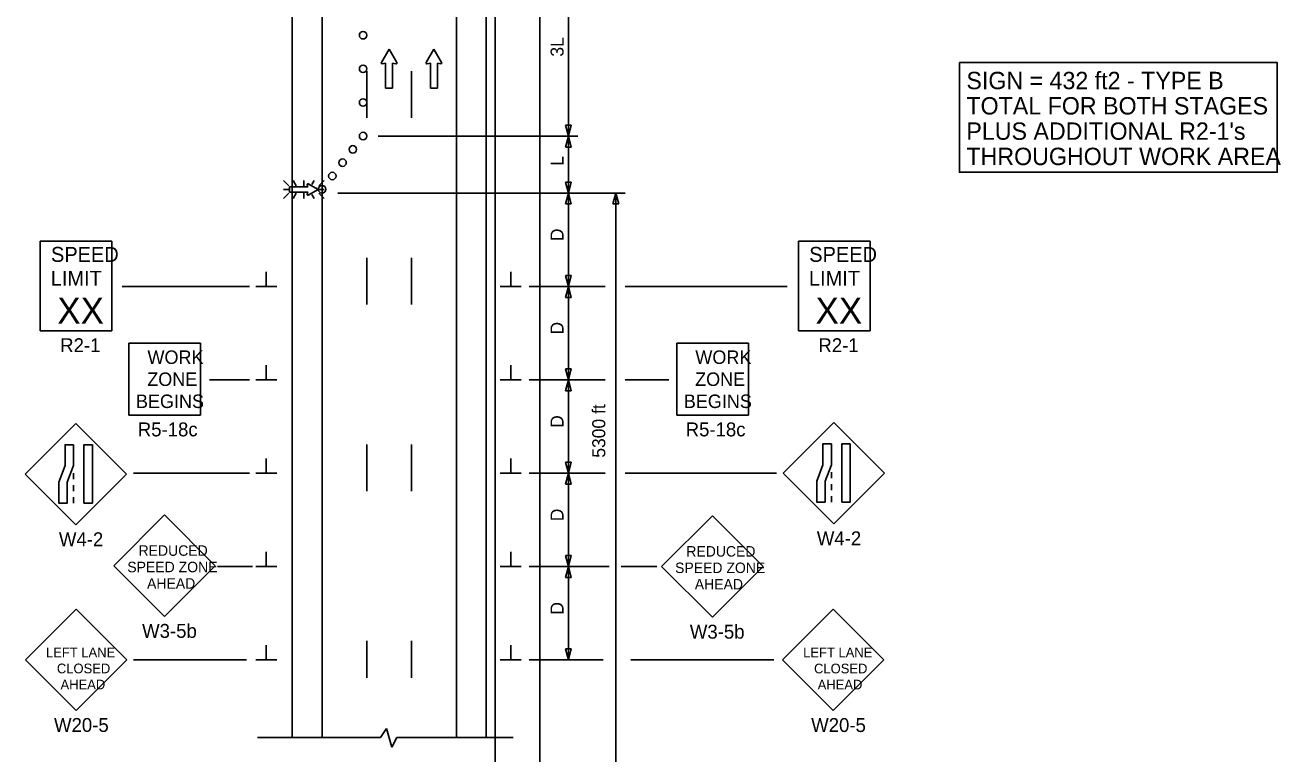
# Model space of a CAD drawing. Extents: x 16590 to 19508, y 5703 to 6974.
# Drawn here: x 16729 to 17402, y 6255 to 6645 of the extents above; entities that cross this region are included whole.
import ezdxf

# ---------------------------------------------------------------- set-up
doc = ezdxf.new("R2010")
doc.units = 0
for name, color, linetype in [('ALI_LEGAL_EX', 7, 'Continuous'), ('MT_SCRATCH_LEVEL_E', 7, 'Continuous'), ('PAVT_EDGE_EX', 7, 'Continuous'), ('TRAFFIC_SIGNS_PR', 7, 'Continuous'), ('TYPICAL_TEXT_DIMEN_EX', 7, 'Continuous'), ('TYPICAL_TEXT_DIMEN_PR', 7, 'Continuous')]:
    doc.layers.add(name, color=color, linetype=linetype)

msp = doc.modelspace()

# ---------------------------------------------------------------- linework, layer by layer
at = {"layer": 'ALI_LEGAL_EX'}
for p, q in [((16980.68, 6974.12), (16980.68, 6155.98)), ((17004.68, 6974.12), (17004.68, 6155.98)), ((16980.68, 6922.21), (16980.68, 6058.3)), ((17004.68, 6922.21), (17004.68, 6058.3))]:
    msp.add_line(p, q, dxfattribs=at)
for points in [[(16911.96, 6620.69), (16911.96, 6595.69)], [(16935.96, 6620.69), (16935.96, 6595.69)], [(16911.96, 6520.69), (16911.96, 6495.69)], [(16935.96, 6520.69), (16935.96, 6495.69)], [(16911.96, 6420.69), (16911.96, 6395.69)], [(16935.96, 6420.69), (16935.96, 6395.69)], [(16911.96, 6315.64), (16911.96, 6295.69)], [(16935.96, 6315.64), (16935.96, 6295.69)]]:
    msp.add_lwpolyline(points, dxfattribs=at)
at = {"layer": 'MT_SCRATCH_LEVEL_E'}
for p, q in [((16923.86, 6632.49), (16919.75, 6625.25)), ((16928.01, 6625.25), (16923.86, 6632.49)), ((16947.91, 6632.49), (16943.8, 6625.25)), ((16952.06, 6625.25), (16947.91, 6632.49)), ((16920.23, 6624.57), (16922.01, 6624.88)), ((16922.01, 6624.88), (16922.01, 6611.63)), ((16925.75, 6611.63), (16925.75, 6624.88)), ((16925.75, 6624.88), (16927.53, 6624.57)), ((16944.28, 6624.57), (16946.06, 6624.88)), ((16946.06, 6624.88), (16946.06, 6611.63)), ((16949.8, 6611.63), (16949.8, 6624.88)), ((16949.8, 6624.88), (16951.58, 6624.57)), ((16922.01, 6611.63), (16925.75, 6611.63)), ((16946.06, 6611.63), (16949.8, 6611.63))]:
    msp.add_line(p, q, dxfattribs=at)
for centre, start, end in [((16920.16, 6625.03), 150.42484, 279.96381), ((16927.6, 6625.03), 260.03619, 29.77312), ((16944.21, 6625.03), 150.42484, 279.96381), ((16951.65, 6625.03), 260.03619, 29.77312)]:
    msp.add_arc(centre, 0.463, start, end, dxfattribs=at)
at = {"layer": 'PAVT_EDGE_EX'}
for p, q in [((16871.96, 6927.73), (16871.96, 6263.8)), ((16887.96, 6927.73), (16887.96, 6263.8)), ((16959.96, 6927.73), (16959.96, 6263.8)), ((16975.96, 6927.73), (16975.96, 6263.8))]:
    msp.add_line(p, q, dxfattribs=at)
at = {"layer": 'TRAFFIC_SIGNS_PR'}
for p, q in [((16870.12, 6559.34), (16867.3, 6562.16)), ((16870.12, 6557.31), (16867.3, 6557.31)), ((16874.07, 6559.34), (16872.44, 6562.16)), ((16878.2, 6559.34), (16878.2, 6562.16)), ((16882.39, 6559.98), (16883.65, 6562.16)), ((16889.11, 6562.16), (16886.29, 6559.34)), ((16886.29, 6557.31), (16889.11, 6557.31)), ((16870.12, 6555.28), (16867.3, 6552.46)), ((16872.42, 6552.46), (16874.04, 6555.28)), ((16878.2, 6555.28), (16878.2, 6552.46)), ((16883.67, 6552.46), (16882.47, 6554.55)), ((16889.11, 6552.46), (16886.29, 6555.28)), ((16736.89, 6529.7), (16775.34, 6529.7)), ((16736.89, 6481.64), (16736.89, 6529.7)), ((16775.34, 6481.64), (16775.34, 6529.7)), ((17143.29, 6529.7), (17181.74, 6529.7)), ((17143.29, 6481.64), (17143.29, 6529.7)), ((17181.74, 6481.64), (17181.74, 6529.7)), ((16736.89, 6481.64), (16775.34, 6481.64)), ((17143.29, 6481.64), (17181.74, 6481.64)), ((16784.39, 6436.53), (16784.39, 6474.93)), ((16784.39, 6474.93), (16822.79, 6474.93)), ((16822.79, 6436.53), (16822.79, 6474.93)), ((17078.04, 6436.53), (17078.04, 6474.93)), ((17078.04, 6474.93), (17116.44, 6474.93)), ((17116.44, 6436.53), (17116.44, 6474.93)), ((16784.39, 6436.53), (16822.79, 6436.53)), ((17078.04, 6436.53), (17116.44, 6436.53)), ((16755.95, 6432), (16728.79, 6404.85)), ((16783.1, 6404.85), (16755.95, 6432)), ((17162.19, 6432.52), (17135.04, 6405.37)), ((17189.35, 6405.37), (17162.19, 6432.52)), ((16728.79, 6404.85), (16755.95, 6377.7)), ((16754.7, 6405.34), (16754.7, 6402.14)), ((16755.95, 6377.7), (16783.1, 6404.85)), ((17135.04, 6405.37), (17162.19, 6378.21)), ((17160.95, 6405.86), (17160.95, 6402.66)), ((17162.19, 6378.21), (17189.35, 6405.37)), ((16754.7, 6398.94), (16754.7, 6395.74)), ((17160.95, 6399.46), (17160.95, 6396.26)), ((16754.7, 6392.54), (16754.7, 6389.34)), ((17160.95, 6393.06), (17160.95, 6389.86)), ((16803.56, 6383), (16776.37, 6355.82)), ((16830.74, 6355.82), (16803.56, 6383)), ((17097.14, 6382.59), (17069.96, 6355.4)), ((17124.33, 6355.4), (17097.14, 6382.59)), ((16776.37, 6355.82), (16803.56, 6328.63)), ((16803.56, 6328.63), (16830.74, 6355.82)), ((17069.96, 6355.4), (17097.14, 6328.21)), ((17097.14, 6328.21), (17124.33, 6355.4)), ((16756.12, 6332.56), (16728.97, 6305.4)), ((16783.27, 6305.4), (16756.12, 6332.56)), ((17161.94, 6332.51), (17134.79, 6305.36)), ((17189.09, 6305.36), (17161.94, 6332.51)), ((16728.97, 6305.4), (16756.12, 6278.25)), ((16756.12, 6278.25), (16783.27, 6305.4)), ((17134.79, 6305.36), (17161.94, 6278.21)), ((17161.94, 6278.21), (17189.09, 6305.36))]:
    msp.add_line(p, q, dxfattribs=at)
for points in [[(16880.03, 6554.63), (16880.26, 6555.93), (16870.54, 6555.93), (16870.54, 6558.67), (16880.26, 6558.67), (16880.03, 6559.97)], [(16880.53, 6560.33), (16885.84, 6557.31), (16880.53, 6554.27)]]:
    msp.add_lwpolyline(points, dxfattribs=at)
for points in [[(16754.7, 6420.59), (16754.7, 6409.41), (16751.36, 6400.52), (16751.36, 6389.34), (16746.86, 6389.34), (16746.86, 6400.52), (16750.21, 6409.41), (16750.21, 6420.59)], [(16764.84, 6420.59), (16764.84, 6389.34), (16760.34, 6389.34), (16760.34, 6420.59)], [(17160.95, 6421.1), (17160.95, 6409.92), (17157.6, 6401.04), (17157.6, 6389.86), (17153.11, 6389.86), (17153.11, 6401.04), (17156.45, 6409.92), (17156.45, 6421.1)], [(17171.08, 6421.1), (17171.08, 6389.86), (17166.59, 6389.86), (17166.59, 6421.1)]]:
    msp.add_lwpolyline(points, close=True, dxfattribs=at)
for centre in [(16909.95, 6639.92), (16909.95, 6621.92), (16909.95, 6603.92), (16909.95, 6585.92), (16909.95, 6585.92), (16909.95, 6585.92), (16909.95, 6585.92), (16904.45, 6578.79), (16898.95, 6571.66), (16893.46, 6564.53), (16887.96, 6557.41)]:
    msp.add_circle(centre, 2, dxfattribs=at)
for centre, start, end in [((16880.37, 6560.03), 61.10835, 189.26922), ((16880.37, 6554.57), 170.04067, 298.51671)]:
    msp.add_arc(centre, 0.341, start, end, dxfattribs=at)
at = {"layer": 'TYPICAL_TEXT_DIMEN_EX'}
msp.add_lwpolyline([(17229.59, 6625.26), (17399.96, 6625.26), (17399.96, 6566.51), (17229.59, 6566.51)], close=True, dxfattribs=at)
at = {"layer": 'TYPICAL_TEXT_DIMEN_PR'}
for p, q in [((17020.05, 6677.97), (17019.96, 6585.92)), ((17019.96, 6585.92), (17018.39, 6591.78)), ((17018.39, 6591.78), (17019.96, 6591.78)), ((17019.96, 6591.78), (17021.53, 6591.78)), ((17021.53, 6591.78), (17019.96, 6585.92)), ((17024.96, 6585.92), (16918.04, 6585.92)), ((17018.39, 6580.06), (17019.96, 6585.92)), ((17019.96, 6555.41), (17019.96, 6585.92)), ((17019.96, 6585.92), (17021.53, 6580.06)), ((17019.96, 6580.06), (17018.39, 6580.06)), ((17021.53, 6580.06), (17019.96, 6580.06)), ((17019.96, 6555.41), (17018.39, 6561.27)), ((17018.39, 6561.27), (17019.96, 6561.27)), ((17019.96, 6561.27), (17021.53, 6561.27)), ((17021.53, 6561.27), (17019.96, 6555.41)), ((16896.35, 6555.41), (17050.39, 6555.41)), ((17018.39, 6549.55), (17019.96, 6555.41)), ((17019.96, 6549.55), (17018.39, 6549.55)), ((17019.96, 6555.41), (17019.96, 6505.41)), ((17019.96, 6555.41), (17021.53, 6549.55)), ((17021.53, 6549.55), (17019.96, 6549.55)), ((17043.82, 6549.55), (17045.39, 6555.41)), ((17045.39, 6549.55), (17043.82, 6549.55)), ((17045.39, 6555.41), (17045.39, 6202.2)), ((17045.39, 6555.41), (17046.96, 6549.55)), ((17046.96, 6549.55), (17045.39, 6549.55)), ((16858.07, 6505.41), (16858.07, 6513.19)), ((16989.08, 6505.41), (16989.08, 6513.19)), ((17019.96, 6505.41), (17018.39, 6511.27)), ((17018.39, 6511.27), (17019.96, 6511.27)), ((17019.96, 6511.27), (17021.53, 6511.27)), ((17021.53, 6511.27), (17019.96, 6505.41)), ((16849.02, 6505.41), (16780.84, 6505.41)), ((16863.7, 6505.41), (16852.45, 6505.41)), ((16994.71, 6505.41), (16983.46, 6505.41)), ((17039.74, 6505.41), (16998.96, 6505.41)), ((17018.39, 6499.55), (17019.96, 6505.41)), ((17019.96, 6505.41), (17019.96, 6455.41)), ((17019.96, 6505.41), (17021.53, 6499.55)), ((17137.17, 6505.41), (17050.39, 6505.41)), ((17019.96, 6499.55), (17018.39, 6499.55)), ((17021.53, 6499.55), (17019.96, 6499.55)), ((16858.07, 6455.41), (16858.07, 6463.19)), ((16989.08, 6455.41), (16989.08, 6463.19)), ((16849.02, 6455.41), (16827.64, 6455.41)), ((16863.7, 6455.41), (16852.45, 6455.41)), ((16994.71, 6455.41), (16983.46, 6455.41)), ((17039.74, 6455.41), (16998.96, 6455.41)), ((17019.96, 6455.41), (17018.39, 6461.27)), ((17018.39, 6461.27), (17019.96, 6461.27)), ((17018.39, 6449.55), (17019.96, 6455.41)), ((17019.96, 6461.27), (17021.53, 6461.27)), ((17021.53, 6461.27), (17019.96, 6455.41)), ((17019.96, 6455.41), (17019.96, 6405.41)), ((17019.96, 6455.41), (17021.53, 6449.55)), ((17073.74, 6455.41), (17050.45, 6455.41)), ((17019.96, 6449.55), (17018.39, 6449.55)), ((17021.53, 6449.55), (17019.96, 6449.55)), ((16858.07, 6405.41), (16858.07, 6413.19)), ((16989.08, 6405.41), (16989.08, 6413.19)), ((17019.96, 6405.41), (17018.39, 6411.27)), ((17018.39, 6411.27), (17019.96, 6411.27)), ((17019.96, 6411.27), (17021.53, 6411.27)), ((17021.53, 6411.27), (17019.96, 6405.41)), ((16849.02, 6405.41), (16786.8, 6405.41)), ((16863.7, 6405.41), (16852.45, 6405.41)), ((16994.71, 6405.41), (16983.46, 6405.41)), ((17039.74, 6405.41), (16998.96, 6405.41)), ((17018.39, 6399.55), (17019.96, 6405.41)), ((17019.96, 6405.41), (17019.96, 6355.41)), ((17019.96, 6405.41), (17021.53, 6399.55)), ((17131.57, 6405.41), (17050.39, 6405.41)), ((17019.96, 6399.55), (17018.39, 6399.55)), ((17021.53, 6399.55), (17019.96, 6399.55)), ((16858.07, 6355.41), (16858.07, 6363.19)), ((16989.08, 6355.41), (16989.08, 6363.19)), ((17019.96, 6355.41), (17018.39, 6361.27)), ((17018.39, 6361.27), (17019.96, 6361.27)), ((17019.96, 6361.27), (17021.53, 6361.27)), ((17021.53, 6361.27), (17019.96, 6355.41)), ((16850.63, 6355.41), (16831.98, 6355.41)), ((16863.7, 6355.41), (16852.45, 6355.41)), ((16994.71, 6355.41), (16983.46, 6355.41)), ((17041.77, 6355.41), (16998.96, 6355.41)), ((17018.39, 6349.55), (17019.96, 6355.41)), ((17019.96, 6355.41), (17019.96, 6305.41)), ((17019.96, 6355.41), (17021.53, 6349.55)), ((17067.45, 6355.41), (17048.36, 6355.41)), ((17019.96, 6349.55), (17018.39, 6349.55)), ((17021.53, 6349.55), (17019.96, 6349.55)), ((16858.07, 6305.41), (16858.07, 6313.19)), ((16989.08, 6305.41), (16989.08, 6313.19)), ((17019.96, 6305.41), (17018.39, 6311.27)), ((17018.39, 6311.27), (17019.96, 6311.27)), ((17019.96, 6311.27), (17021.53, 6311.27)), ((17021.53, 6311.27), (17019.96, 6305.41)), ((16786.8, 6305.41), (16847.41, 6305.41)), ((16863.7, 6305.41), (16852.45, 6305.41)), ((16994.71, 6305.41), (16983.46, 6305.41)), ((17038.56, 6305.41), (16998.96, 6305.41)), ((17130.13, 6305.41), (17053.51, 6305.41)), ((16922.56, 6268.6), (16919.31, 6263.8)), ((16925.3, 6258.66), (16922.56, 6268.6)), ((16919.31, 6263.8), (16853.36, 6263.8)), ((16928.05, 6263.8), (16925.3, 6258.66)), ((16990.38, 6263.8), (16928.05, 6263.8))]:
    msp.add_line(p, q, dxfattribs=at)

# ---------------------------------------------------------------- texts
at = {"layer": 'TRAFFIC_SIGNS_PR'}
for s, height, p in [('SPEED', 8.01, (16742.67, 6518.55)), ('SPEED', 8.01, (17149.07, 6518.55)), ('LIMIT', 8.01, (16742.51, 6505.73)), ('LIMIT', 8.01, (17148.91, 6505.73)), ('XX', 14.048, (16746.02, 6485.4)), ('XX', 14.048, (17152.42, 6485.4)), ('R2-1', 7.449, (16747.58, 6470.19)), ('R2-1', 7.449, (17153.98, 6470.19)), ('WORK', 7.217, (16794.39, 6463.89)), ('WORK', 7.217, (17088.04, 6463.89)), ('ZONE', 7.217, (16794.27, 6452.08)), ('ZONE', 7.217, (17087.92, 6452.08)), ('BEGINS', 7.217, (16788.2, 6440.27)), ('BEGINS', 7.217, (17081.85, 6440.27)), ('R5-18c', 7.44, (16789.2, 6425.09)), ('R5-18c', 7.44, (17082.85, 6425.09)), ('W4-2', 7.44, (17153.15, 6366.77)), ('W4-2', 7.44, (16746.91, 6366.26)), ('REDUCED', 5.607, (16789.6, 6361.13)), ('REDUCED', 5.607, (17083.18, 6360.71)), ('SPEED ZONE', 5.607, (16783.58, 6352.32)), ('SPEED ZONE', 5.607, (17077.17, 6351.9)), ('AHEAD', 5.607, (16794.15, 6343.51)), ('AHEAD', 5.607, (17087.74, 6343.09)), ('W3-5b', 7.449, (16791.49, 6317.18)), ('W3-5b', 7.449, (17085.08, 6316.76)), ('LEFT LANE', 5.2, (16740, 6306.8)), ('LEFT LANE', 5.2, (17145.82, 6306.76)), ('CLOSED', 5.2, (16745.83, 6298.2)), ('CLOSED', 5.2, (17151.66, 6298.16)), ('AHEAD', 5.2, (16747.78, 6289.6)), ('AHEAD', 5.2, (17153.6, 6289.56)), ('W20-5', 7.44, (16744.29, 6266.81)), ('W20-5', 7.44, (17150.12, 6266.77))]:
    msp.add_text(s, height=height, dxfattribs=at).set_placement(p)
at = {"layer": 'TYPICAL_TEXT_DIMEN_EX'}
for s, p in [('SIGN = 432 ft2 - TYPE B', (17233.32, 6611.02)), ('TOTAL FOR BOTH STAGES', (17233.32, 6597.47)), ("PLUS ADDITIONAL R2-1's", (17233.32, 6583.92)), ('THROUGHOUT WORK AREA', (17233.32, 6570.37))]:
    msp.add_text(s, height=9.3, dxfattribs=at).set_placement(p)
at = {"layer": 'TYPICAL_TEXT_DIMEN_PR'}
for s, p in [('3L', (17017.44, 6628.45)), ('L', (17017.4, 6570.02)), ('D', (17017.4, 6529.63)), ('D', (17017.4, 6479.63)), ('5300 ft', (17039.76, 6413.65)), ('D', (17017.4, 6429.63)), ('D', (17017.4, 6379.63)), ('D', (17017.4, 6329.63))]:
    msp.add_text(s, height=7, rotation=90, dxfattribs=at).set_placement(p)

doc.saveas('drawing.dxf')
